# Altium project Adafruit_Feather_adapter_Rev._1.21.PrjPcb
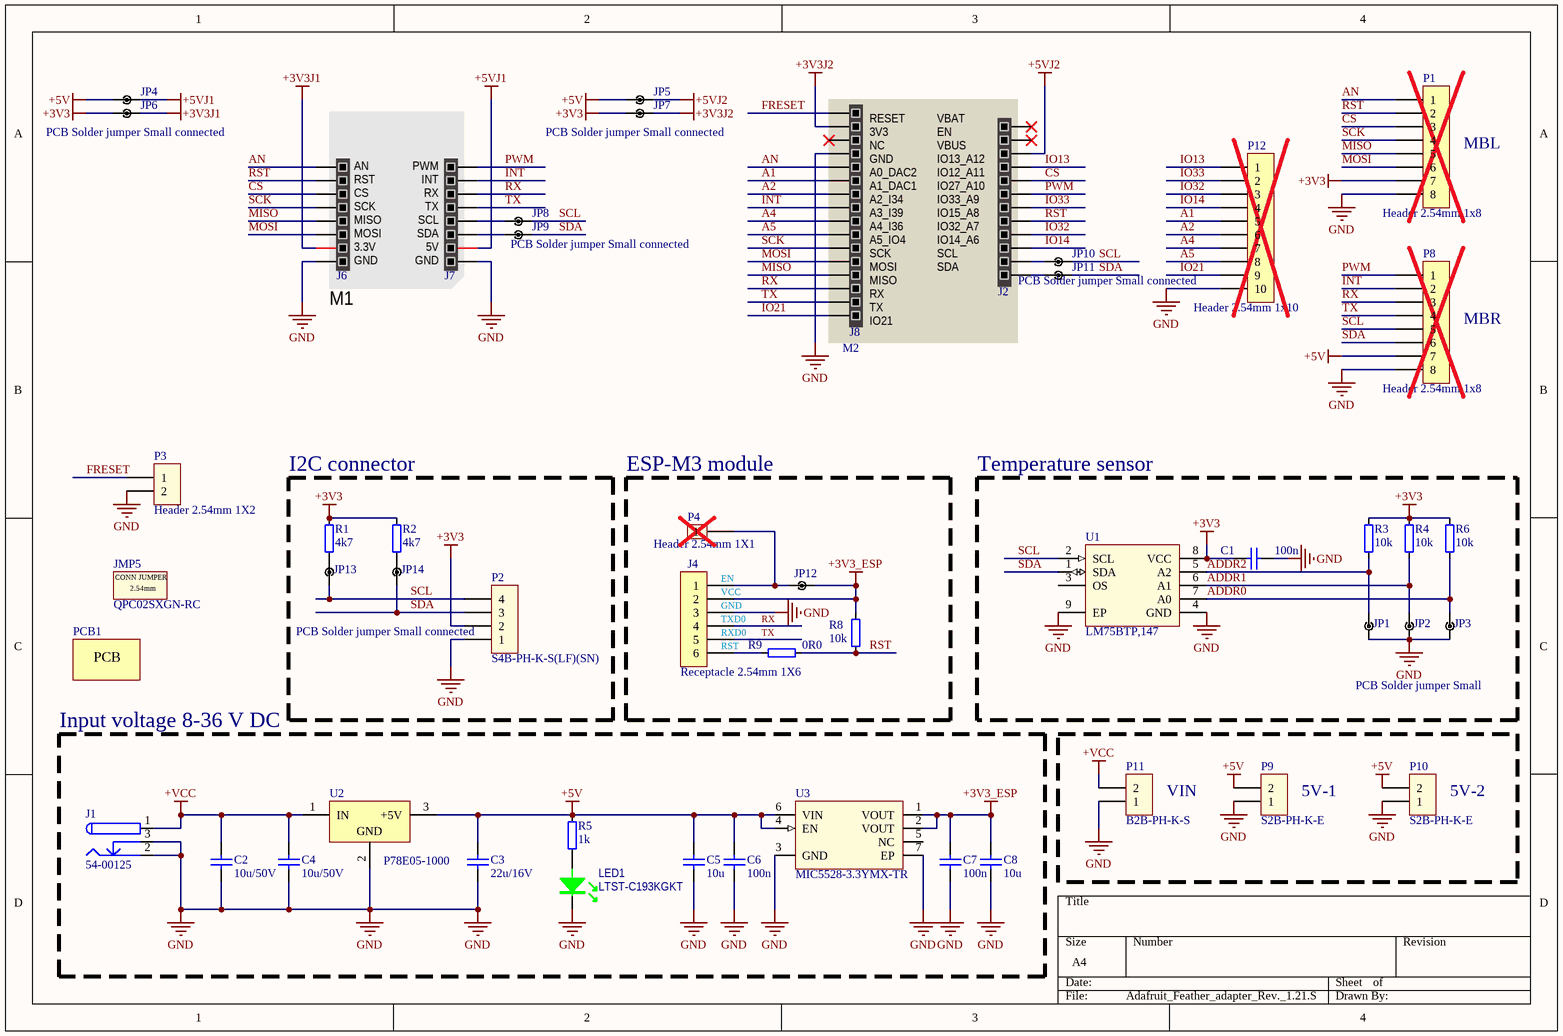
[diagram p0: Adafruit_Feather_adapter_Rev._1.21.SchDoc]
1 sheet, 53 parts. Net scope: global (net labels, ports and power ports of the same name join across sheets).
Board file: Adafruit_Feather_adapter_Rev._1.21.PcbDoc

## Sheet Adafruit_Feather_adapter_Rev._1.21.SchDoc: =ProjectName
size A4; Author: Tobias Zvonc; DrawnBy: Tobias Zvonc; Engineer: Tobias Zvonc

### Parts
C1  100n  [C-0603]
C2  10u/50V  [C-1210]
C3  22u/16V  [C-1210]
C4  10u/50V  [C-1210]
C5  10u  [C-1206]
C6  100n  [C-0603]
C7  100n  [C-0603]
C8  10u  [C-1206]
J1  54-00125  [Conn_54-00125]
J2  CES-112-01-T-S  [SCOKET12X01]  (value not drawn)
J4  Receptacle 2.54mm 1X6  [Receptacle 2.54mm 1X6]
J6  SSQ-108-01-T-S  [MIKROE_ROW_1x8]  (value not drawn)
J7  SSQ-108-01-T-S  [MIKROE_ROW_1x8]  (value not drawn)
J8  SLW-116-01-T-S  [SCOKET16X01]  (value not drawn)
JMP5  QPC02SXGN-RC  (mechanical)
JP1  PCB Solder jumper Small  [PCB solder jumper small]  (value not drawn)  (no BOM)
JP2  PCB Solder jumper Small  [PCB solder jumper small]  (value not drawn)  (no BOM)
JP3  PCB Solder jumper Small  [PCB solder jumper small]  (no BOM)
JP4  PCB Solder jumper Small connected  [PCB solder jumper small - connected]  (value not drawn)  (net tie, no BOM)
JP5  PCB Solder jumper Small connected  [PCB solder jumper small - connected]  (value not drawn)  (net tie, no BOM)
JP6  PCB Solder jumper Small connected  [PCB solder jumper small - connected]  (net tie, no BOM)
JP7  PCB Solder jumper Small connected  [PCB solder jumper small - connected]  (net tie, no BOM)
JP8  PCB Solder jumper Small connected  [PCB solder jumper small - connected]  (value not drawn)  (net tie, no BOM)
JP9  PCB Solder jumper Small connected  [PCB solder jumper small - connected]  (net tie, no BOM)
JP10  PCB Solder jumper Small connected  [PCB solder jumper small - connected]  (value not drawn)  (net tie, no BOM)
JP11  PCB Solder jumper Small connected  [PCB solder jumper small - connected]  (net tie, no BOM)
JP12  PCB Solder jumper Small connected  [PCB solder jumper small - connected]  (value not drawn)  (net tie, no BOM)
JP13  PCB Solder jumper Small connected  [PCB solder jumper small - connected]  (net tie, no BOM)
JP14  PCB Solder jumper Small connected  [PCB solder jumper small - connected]  (value not drawn)  (net tie, no BOM)
LED1  LTST-C193KGKT  [LED-0603]
M1  MIKROBUS HOST  [MIKROBUS HOST CONN.]  (value not drawn)  (no BOM)
M2  FEATHER  [FEATHERHOST]  (value not drawn)  (no BOM)
P1  Header 2.54mm 1x8  [CONN_Header_2.54mm_1X8]
P2  S4B-PH-K-S(LF)(SN)  [Conn_S4B-PH-K-S]
P3  Header 2.54mm 1X2  [CONN_Header_2.54mm_1X2]
P4  Header 2.54mm 1X1  [Header 2.54mm 1X1]
P8  Header 2.54mm 1x8  [CONN_Header_2.54mm_1X8]
P9  S2B-PH-K-E  [Conn_S2B-PH-K-E]
P10  S2B-PH-K-E  [Conn_S2B-PH-K-E]
P11  B2B-PH-K-S  [Conn B2B-PH-K-S]
P12  Header 2.54mm 1x10  [CONN_Header_2.54mm_1X10]
PCB1  PCB  (value not drawn)  (mechanical)
R1  4k7  [R-0603]
R2  4k7  [R-0603]
R3  10k  [R-0603]
R4  10k  [R-0603]
R5  1k  [R-0603]
R6  10k  [R-0603]
R8  10k  [R-0603]
R9  0R0  [R-0603]
U1  LM75BTP,147  [DFN50P200X300X75-8T150]
U2  P78E05-1000  [SIP-3]
U3  MIC5528-3.3YMX-TR  [DFN40P120X120X40-6T30X94]

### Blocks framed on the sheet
I2C connector: JP13 JP14 P2 R1 R2
ESP-M3 module: J4 JP12 P4 R8 R9
Temperature sensor: C1 JP1-JP3 R3 R4 R6 U1
Input voltage 8-36 V DC: C2-C8 J1 LED1 R5 U2 U3

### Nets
+3V3: C1.1 JP6.1 JP7.1 P1.7 P2.2 R1.2 R2.2 R3.2 R4.2 R6.2 U1.8(VCC)
+3V3_ESP: C7.2 C8.2 J4.2 JP12.2 R8.2 U3.1(VOUT) U3.2(VOUT)
+3V3J1: J6.7 JP6.2
+3V3J2: J8.2 JP7.2
+5V: C3.2 C5.2 C6.2 JP4.1 JP5.1 P8.7 P9.2 P10.2 R5.2 U2.3(+5V) U3.4(EN) U3.6(VIN)
+5VJ1: J7.7 JP4.2
+5VJ2: J2.3 JP5.2
+VCC: C2.2 C4.2 J1.1 P11.2 U2.1(IN)
GND: C1.2 C2.1 C3.1 C4.1 C5.1 C6.1 C7.1 C8.1 J1.2 J1.3 J4.3 J6.8 J7.8 J8.4 JP1.2 JP2.2 JP3.2 LED1.2(A) P1.8 P2.1 P3.2 P8.8 P9.1 P10.1 P11.1 P12.10 U1.4(GND) U1.9(EP) U2.2(GND) U3.3(GND) U3.7(EP)
A1: J8.6 P12.5
A2: J8.7 P12.6
A4: J8.9 P12.7
A5: J8.10 P12.8
ADDR0: JP3.1 R6.1 U1.7(A0)
ADDR1: JP2.1 R4.1 U1.6(A1)
ADDR2: JP1.1 R3.1 U1.5(A2)
AN: J6.1 J8.5 P1.1
CS: J2.5 J6.3 P1.3
FRESET: J8.1 P3.1
INT: J7.2 J8.8 P8.2
IO13: J2.4 P12.1
IO14: J2.10 P12.4
IO21: J8.16 P12.9
IO32: J2.9 P12.3
IO33: J2.7 P12.2
MISO: J6.5 J8.13 P1.5
MOSI: J6.6 J8.12 P1.6
PWM: J2.6 J7.1 P8.1
RST: J2.8 J6.2 P1.2 R8.1 R9.1
RX: J4.4 J7.3 J8.14 P8.3
SCK: J6.4 J8.11 P1.4
SCL: JP8.2 JP10.2 JP13.1 P2.4 P8.5 U1.2(SCL)
SDA: JP9.2 JP11.2 JP14.1 P2.3 P8.6 U1.1(SDA)
TX: J4.5 J7.4 J8.15 P8.4
NetJ2_11: J2.11 JP10.1
NetJ2_12: J2.12 JP11.1
NetJ4_1: J4.1 JP12.1 P4.1
NetJ4_6: J4.6 R9.2
NetJ7_5: J7.5 JP8.1
NetJ7_6: J7.6 JP9.1
NetJP13_2: JP13.2 R1.1
NetJP14_2: JP14.2 R2.1
NetLED1_1: LED1.1(K) R5.1

Not connected (* = marked no-connect by the designer): J2 1* 2*; J8 3*; U1 3(OS); U3 5(NC)

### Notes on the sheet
- (near P1) MBL
- (near P8) MBR
- (near J4) EN
- (near J4) VCC
- (near J4) GND
- (near J4) TXD0
- (near J4) RXD0
- (near J4) RST
- (near P11) VIN
- (near P9) 5V-1
- (near P10) 5V-2

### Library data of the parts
C1 C6 C7 = C0603-100n-50V-X7R: Capacitor ceramic 100n X7R 50V 0603
C2 C4 = C1210-10u-50V-X7R: Capacitor ceramic 10u ±10% X7R 50V 1210; Manufacturer: Samsung Electro-Mechanics; Manufacturer Part Number: CL32B106KBJNNWE
C3 = C1210-22u-16V-X7R: Capacitor ceramic 22u ±15% X7R 16V 1210; Manufacturer: Murata; Manufacturer Part Number: GCM32ER71C226ME19L; Note: Promijenjen DigiKey PN na dobavljivu komponentu
C5 C8 = C1206-10u-16V-X7R: Capacitor ceramic 10u ±10 X7R 16V 1206
J1 = Conn Barrel 54-00125: Barrel Power Connector, 1.1/3.5mm (ID/OD), 48V/3.5A; Manufacturer: Tensility International Corp
J2 = ROW_01X12: Manufacturer: Samtec
J4 = Conn Receptacle 2.54mm 1X6: 2.54mm pitch 6 pin (1x6) top entry wire to board connector THT; Manufacturer: Samtec; Manufacturer Part Number: SSQ-106-01-T-S
J6 J7 = MIKROE_ROW_01X08: Manufacturer: Samtec
J8 = ROW_01X16: Manufacturer: Samtec
JMP5 = Conn Jumper 2.54mm: CONN JUMPER SHORTING .100" GOLD; Manufacturer: Sullins Connector Solutions
JP4-JP14 = PCB Solder jumper Small connected: PCB Solder jumper Small - connected
LED1 = LTST-C193KGKT: Standard LEDs - SMD Green, 571nm 12mcd, 5mA; Manufacturer: LiteON; PartNumber: LTST-C193KGKT-5A; Fixed: NO
M1 = MIKROBUS HOST: mikroBUS Host Socket
P1 P8 = Conn Header 2.54mm 1X8: 2.54mm pitch 8 pin (1x8) top entry wire to board connector THT; Manufacturer: Sullins Connector Solutions; Manufacturer Part Number: PREC008SAAN-RC
P2 = Conn S4B-PH-K-S(LF)(SN): 2mm pitch 4 pin side entry wire to board connector THT; Manufacturer: JST
P3 = Conn Header 2.54mm 1X2: 2.54mm pitch 2 pin (1x2) top entry wire to board connector THT; Manufacturer: Amphenol ICC (FCI); Manufacturer Part Number: 68001-402HLF
P4 = Conn Header 2.54mm 1X1: 2.54mm pitch 1 pin (1x1) top entry wire to board connector THT
P9 P10 = Conn S2B-PH-K-E: 2.00mm pitch 2 pin side entry wire to board connector, THT; Manufacturer: JST
P11 = Conn B2B-PH-K-S: 2.00mm pitch 2 pin top entry wire to board connector, THT; Manufacturer: JST
P12 = Conn Header 2.54mm 1X10: 2.54mm pitch 10 pin (1x10) top entry wire to board connector THT; Manufacturer: Sullins Connector Solutions; Manufacturer Part Number: PREC010SAAN-RC
PCB1 = PCB: Printed Circuit Board; Manufacturer: Byte Lab
R1 R2 = R0603-4k7-1: Resistor 4k7 ±1% 0603
R3 R4 R6 R8 = R0603-10k-1: Resistor 10k ±1% 0603
R5 = R0603-1k-1: Resistor 1k ±1% 0603
R9 = R0603-0R0: Resistor 0R0 0603
U1 = LM75BTP,147: SENSOR DIGITAL -55C-125C 8HWSON; Manufacturer: NXP USA Inc.
U2 = P78E05-1000: DC-DC NON-ISOLATED, 1.0 A, 8-36 V IN; Manufacturer: CUI Inc.
U3 = MIC5528-3.3YMX-TR: IC REG LINEAR 3.3V 500MA 6TDFN; Manufacturer: Microchip Technology

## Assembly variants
Production: not fitted P1 P4 P8 P12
